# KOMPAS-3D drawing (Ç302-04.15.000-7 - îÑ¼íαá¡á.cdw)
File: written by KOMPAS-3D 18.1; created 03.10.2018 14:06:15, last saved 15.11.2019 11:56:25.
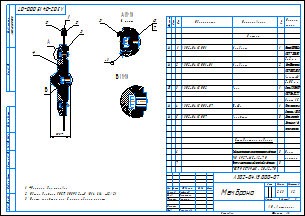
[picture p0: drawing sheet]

Sheet 1: A3, landscape

Document properties: Автор: Милов; Полное имя файла: D:\Мембранные насосы\Мембранный электропривод\А302-00.00.000 - ASTRA-302 (МЭ200)\А302-04.00.000 - Мембранный насос ASTRA-302-PP\А302-04.15.000-7 - Мембрана.cdw; Масса: 2.62614

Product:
- Part/product: (unnamed)
  - Component: Болт с шестигранной головкой с фланцем  / ГОСТ Р 55739-М5 x 20-A2-70  | pos. 7  | Раздел спецификации: Стандартные изделия
  - Component: Гайка шестигранная самостопорящаяся с фланцем / DIN 6927-M5-A2-70  | pos. 6  | Раздел спецификации: Стандартные изделия; Примечание: Нерж. / насечки
  - Component: Заглушка  | designation А302-04.15.007  | pos. 5  | Раздел спецификации: Детали; Форматы листов документа: А4; Примечание: Деталь заготовка  / Заглушка @2~16 / полипропилен
  - Component: Шайба  | designation А302-04.15.003-07  | pos. 4  | Раздел спецификации: Детали; Форматы листов документа: А4; Примечание: Полипропилен / Стержень @2~300
  - Component: Упор  | designation А302-04.15.002  | pos. 3  | Раздел спецификации: Детали; Форматы листов документа: А3; Примечание: Сталь 12Х18Н10Т / ГОСТ 5632-72 / Лист 15
  - Component: Мембрана  | designation А302-04.15.001-01  | pos. 2  | Раздел спецификации: Детали; Форматы листов документа: А4; Примечание: Лист Фторопласт-4 /  ГОСТ 10007-80 Е / "каленный" / S=0,5 мм
  - Component: Мембрана  | designation А302-04.15.001  | pos. 1  | Раздел спецификации: Детали; Форматы листов документа: А4; Примечание: Пластина ІФ-IІ ТМКЩ-C-4 / ГОСТ 7338-90 / S=2 мм

Title block, sheet 1: Наименование: Мембрана; designation: А302-04.15.000 - 07; Масса: 2,63; scale: 1:2; Количество листов документа: 1; organisation: АО «Астерион»; Форматы листов документа: A3; stored path: \\192.168.87.28\Konstructor_doc\Мембранные насосы\Мембранный электропривод\А302-00.00.000 - ASTRA-302 (МЭ200)\3Д ПВХ\А302-01.15.000 - Мембрана.cdw; Разработал: Лифлянд; Проверил: Борисенко; Т. контр.: Лучихин; Утвердил: Григорьева

Views: Вид 1, Местный разрез 1, Вид:2, Выносной элемент 3, Выносной элемент А, Выносной элемент, Выносной элемент Б
Referenced files in D:\Мембранные насосы\Мембранный электропривод\А302-00.00.000 - ASTRA-302 (МЭ200)\3Д ПВХ\: А302-01.15.001-01- Мембрана.m3d, А302-01.15.007 - Заглушка.m3d, А302-01.15.001 - Мембрана.m3d, А302-01.15.002 - Упор.a3d, А302-01.15.003 - Шайба.m3d, А302-01.15.000 - Мембрана.a3d, А302-01.15.001 - Мембрана.cdw, А302-01.15.002 - Упор.m3d, А302-01.15.008 - Кольцо плоское Ф4.m3d, А302-01.15.008 - Кольцо плоское уплотнительное 5-13-10 Ф4.cdw, А302-01.15.009 - Кольцо плоское Ф4.m3d, А302-01.15.007 - Заглушка.cdw, А302-01.15.011 - Заглушка резьбовая.m3d, А302-01.15.011 - Заглушка резьбовая.cdw
Referenced files in Z:\Мембранные насосы\Мембранный электропривод\А302-00.00.000 - ASTRA-302 (МЭ200)\3Д ПВХ\: А302-01.15.000 - Мембрана.a3d, А302-01.15.008 - Кольцо плоское Ф4.m3d
Referenced files in D:\2 Стандартные изделия 3D\Гайки\DIN 6927\: Гайка шестигранная самостопорящаяся с фланцем DIN 6927-M5 - A2-70.m3d
Referenced files in \\192.168.87.28\Konstructor_doc\Мембранные насосы\Мембранный электропривод\А302-00.00.000 - ASTRA-302 (МЭ200)\3Д ПВХ\: А302-01.15.011 - Заглушка резьбовая.cdw
Referenced files in D:\Мембранные насосы\Мембранный электропривод\А302-00.00.000 - ASTRA-302 (МЭ200)\А302-04.00.000 - Мембранный насос ASTRA-302-PP\: А302-02.15.002 - Упор.cdw
Referenced files in C:\Program Files\ASCON\KOMPAS-3D v18\Libs\PartLib\DATA\VAULT\methods\kompas\3d\: PLib_Bolt_1_ISO_1100.m3d, PLib_Nut_ISO_1100.m3d
Referenced files in C:\Program Files\ASCON\KOMPAS-3D V16\Libs\PartLib\DATA\vault\Methods\Kompas\3D\: PLib_Nut_ISO_1100.m3d, PLib_Bolt_1_ISO_1100.m3d
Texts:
  Шайба
  Упор
  Болт с шестигранной головкой с фланцем
  ГОСТ Р  55739-М5 x 25-A2-70
  ГОСТ
  Нерж.
  Нержавеющая сталь
  Гайка шестигранная самостопорящаяся с фланцем
  DIN 6927-M5-A2-70
  Гайка
  шестигранная
  самостопорящаяся
  фланцем
  DIN
  насечки
  Нерж. / насечки
  Кольцо плоское
  уплотнительное 5-13-10 Ф4
  Кольцо плоское  / уплотнительное 5-13-10 Ф4
  ГОСТ Р  55739-М8 x 30-A2-70
  Кольцо плоское Ф4
  Заглушка
  Заглушка резьбовая
  Лента ФУМ
  Лента
  ФУМ
  3D_Doc-graphic.lyt,1.000000-4294967295-203648116615
  Болт с шестигранной головкой с фланцем ГОСТ Р 55739-М5 x 20-A2-70
  Болт
  шестигранной
  головкой
  Пластина ІФ-IІ ТМКЩ-C-4
  ГОСТ 7338-90
  Пластина ІФ-IІ ТМКЩ-C-4 / ГОСТ 7338-90 / S=2 мм
  Лист Фторопласт-4
  ГОСТ 10007-80 Е
  "каленный"
  Лист Фторопласт-4 /  ГОСТ 10007-80 Е / "каленный" / S=0,5 мм
  Сталь 12Х18Н10Т
  ГОСТ 5632-72
  Лист 15
  Сталь 12Х18Н10Т / ГОСТ 5632-72 / Лист 15
  Полипропилен
  Стержень  300
  Полипропилен / Стержень @2~300
  Деталь заготовка
  Заглушка  16
  полипропилен
  Деталь заготовка  / Заглушка @2~16 / полипропилен
  ГОСТ Р 55739-М5 x 20-A2-70
  Шайба (нарощеннАЯ)
  Болт с шестигранной головкой с фланцем ГОСТ Р 55739-М5 x 25-A2-70
  Гайка шестигранная с фланцем ГОСТ Р ИСО 4161 - M5 - A2-70
  Гайка шестигранная самостопорящаяся с фланцем / DIN 6927-M5-A2-70
  Болт с шестигранной головкой с фланцем ГОСТ Р 55739-М8 x 16-A2-70
Dimensions and other numbers on the sheet: 2; 1; 3; 4; 55,5; 8 мест; 5; 6; 7; 10; 9; 11; 8; 12; 100; 41; 48; 1:2; 2,63; 777; 07

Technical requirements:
  *Размеры для справок.
  Общие допуски ГОСТ 30893.2-mK (H14, h14,  t2/2).
  Паять заглушки поз. 5 после сборки пакета.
